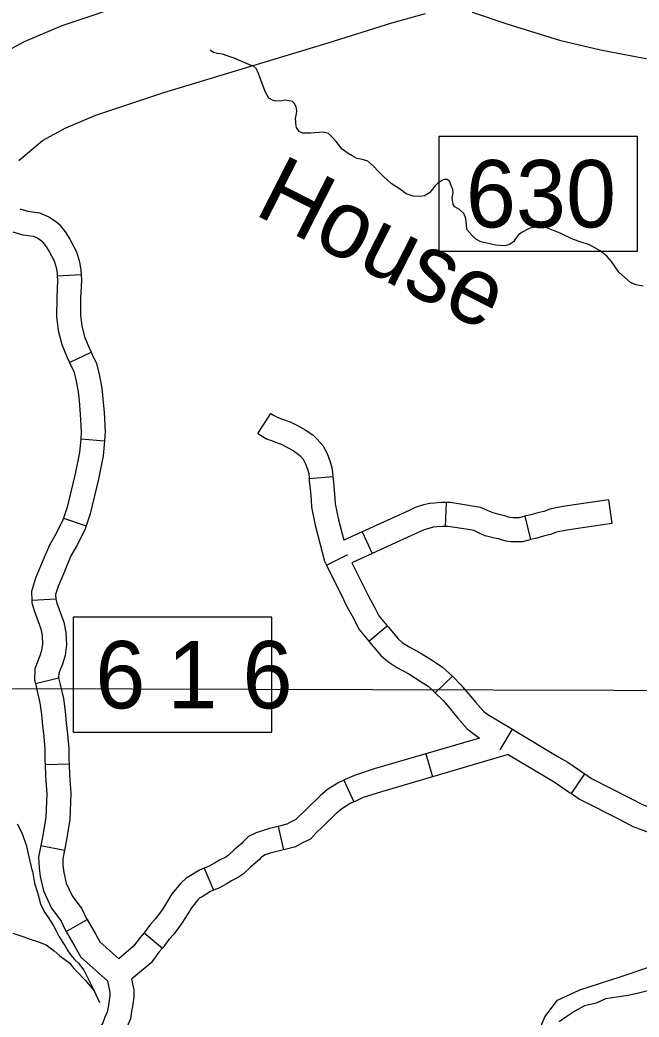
# Model space of a CAD drawing. Extents: x -492261 to -432772, y 1441225 to 1452922.
# Drawn here: x -464243.6 to -464132.7, y 1451313.1 to 1451491.7 of the extents above; entities that cross this region are included whole.
import ezdxf

# ---------------------------------------------------------------- set-up
doc = ezdxf.new("R2010")
doc.units = 0
doc.layers.add('Default', color=7, linetype='Continuous')

msp = doc.modelspace()

# ---------------------------------------------------------------- linework, layer by layer
at = {"layer": 'Default'}
for p, q in [((-464236.88, 1451445.9), (-464232.6, 1451446.1)), ((-464234.68, 1451430.36), (-464230.8, 1451432.18)), ((-464200.98, 1451417.65), (-464198.64, 1451421.24)), ((-464232.68, 1451416.69), (-464228.41, 1451416.31)), ((-464191.78, 1451409.55), (-464187.51, 1451409.91)), ((-464167.23, 1451405.28), (-464167.38, 1451400.99)), ((-464138.18, 1451405.73), (-464137.57, 1451401.49)), ((-464235.79, 1451402.47), (-464231.73, 1451401.11)), ((-464153.15, 1451402.81), (-464152.15, 1451398.65)), ((-464182.25, 1451400.03), (-464180.47, 1451396.13)), ((-464188.67, 1451394.03), (-464184.84, 1451395.94)), ((-464241.44, 1451387.81), (-464237.16, 1451388.02)), ((-464181.1, 1451380.47), (-464177.81, 1451383.22)), ((-464240.8, 1451372.85), (-464236.63, 1451373.85)), ((-464169.17, 1451371.18), (-464166.12, 1451374.2)), ((-464157.55, 1451360.99), (-464155.35, 1451364.67)), ((-464170.89, 1451360.28), (-464169.69, 1451356.16)), ((-464239.06, 1451358.34), (-464234.77, 1451358.48)), ((-464144.8, 1451353.15), (-464142.4, 1451356.7)), ((-464185.53, 1451355.55), (-464183.74, 1451351.66)), ((-464197.33, 1451347.25), (-464196.33, 1451343.08)), ((-464239.82, 1451343.83), (-464235.61, 1451343.02)), ((-464210.54, 1451339.78), (-464208.88, 1451335.84)), ((-464235.26, 1451328.44), (-464231.55, 1451330.58)), ((-464221.33, 1451328.22), (-464218.05, 1451325.47))]:
    msp.add_line(p, q, dxfattribs=at)
for points in [[(-464249.21, 1451484.39), (-464242.77, 1451487.85), (-464236.03, 1451490.72), (-464222.97, 1451495.04)], [(-464243.78, 1451466.55), (-464239.52, 1451470.13), (-464235.34, 1451472.39), (-464229.98, 1451474.67), (-464217.8, 1451478.69), (-464188.35, 1451487.59), (-464176.95, 1451491.17), (-464170.92, 1451492.87)], [(-464162.57, 1451493.1), (-464156.37, 1451490.99), (-464146.94, 1451488.06), (-464139.57, 1451486.35), (-464130.53, 1451484.62), (-464120.94, 1451483.25), (-464108.9, 1451483.08), (-464100.34, 1451482.21), (-464093.37, 1451481.26), (-464088.93, 1451481.06), (-464081.54, 1451481.13), (-464073.63, 1451482.95), (-464059.42, 1451485.52), (-464054.97, 1451485.57), (-464051.76, 1451485.07), (-464046.64, 1451483.57), (-464039.49, 1451480.26), (-464037.02, 1451479.36), (-464034.15, 1451478.64), (-464027.99, 1451478.02)], [(-464158.33, 1451451.38), (-464159.42, 1451451.6), (-464161.02, 1451451.98), (-464161.94, 1451452.43), (-464162.57, 1451453.11), (-464163.5, 1451454.18), (-464163.56, 1451454.98), (-464163.69, 1451456.13), (-464164.04, 1451457.04), (-464164.85, 1451457.77), (-464165.65, 1451458.22), (-464166, 1451458.73), (-464166.18, 1451459.76), (-464165.96, 1451460.79), (-464166.02, 1451461.36), (-464166.32, 1451462.05), (-464166.61, 1451462.84), (-464167.07, 1451463.12), (-464167.64, 1451463.12), (-464168.6, 1451462.59), (-464169.28, 1451461.95), (-464169.9, 1451461.09), (-464170.24, 1451460.74), (-464171.09, 1451460.22), (-464171.89, 1451460.09), (-464173.14, 1451460.14), (-464174.4, 1451460.58), (-464175.43, 1451461.31), (-464177.1, 1451462.44), (-464178.42, 1451463.68), (-464179.4, 1451464.59), (-464180.27, 1451465.49), (-464181.25, 1451466.4), (-464182.22, 1451466.73), (-464183.25, 1451466.89), (-464184.05, 1451467.34), (-464184.8, 1451467.79), (-464185.83, 1451468.57), (-464186.93, 1451469.94), (-464187.62, 1451470.73), (-464188.31, 1451471.35), (-464189.17, 1451471.63), (-464191.51, 1451471.43), (-464192.88, 1451471.41), (-464193.57, 1451471.75), (-464194.03, 1451472.43), (-464194.09, 1451472.66), (-464194.22, 1451474.03), (-464194.05, 1451474.89), (-464193.95, 1451475.35), (-464194.01, 1451475.86), (-464194.07, 1451476.09), (-464194.36, 1451476.72), (-464194.76, 1451477.11), (-464195.68, 1451477.27), (-464196.13, 1451477.33), (-464196.65, 1451477.21), (-464197.73, 1451477.14), (-464198.19, 1451477.3), (-464198.99, 1451477.69), (-464199.57, 1451478.77), (-464200.15, 1451480.14), (-464200.57, 1451481.45), (-464200.8, 1451481.96), (-464201.21, 1451482.93), (-464201.73, 1451483.44), (-464202.42, 1451483.66), (-464203.1, 1451483.94), (-464204.25, 1451484.44), (-464205.22, 1451484.83), (-464206.42, 1451485.28), (-464207.28, 1451485.55), (-464208.2, 1451485.71), (-464208.88, 1451485.88), (-464209.49, 1451486.27)], [(-464168.51, 1451450.3), (-464132.94, 1451450.3), (-464132.94, 1451470.85), (-464168.51, 1451470.85), (-464168.51, 1451450.3)], [(-464243.56, 1451457.88), (-464242.16, 1451457.45), (-464240.05, 1451457.17), (-464238.39, 1451456.47), (-464237.4, 1451455.8), (-464236.55, 1451455.14), (-464235.48, 1451453.73), (-464234.62, 1451452.45), (-464233.42, 1451450.16), (-464232.92, 1451448.37), (-464232.63, 1451446.88), (-464232.6, 1451446.1)], [(-464131.97, 1451444.01), (-464133.17, 1451444.29), (-464133.57, 1451444.4), (-464134.2, 1451444.67), (-464136.33, 1451446.54), (-464137.6, 1451448.47), (-464138.47, 1451449.37), (-464139.62, 1451450.33), (-464141.57, 1451451.4), (-464143.06, 1451451.9), (-464144.6, 1451452.45), (-464146.78, 1451453.51), (-464149.18, 1451454.46), (-464150.44, 1451454.67), (-464151.13, 1451454.67), (-464152.38, 1451454.37), (-464153.63, 1451453.72), (-464154.3, 1451453.2), (-464154.87, 1451452.45), (-464155.15, 1451451.99), (-464155.88, 1451451.47), (-464156.74, 1451451.23), (-464158.33, 1451451.38)], [(-464244.82, 1451453.78), (-464243.07, 1451453.24), (-464241.18, 1451452.99), (-464240.44, 1451452.68), (-464239.93, 1451452.34), (-464239.63, 1451452.1), (-464238.97, 1451451.24), (-464238.32, 1451450.26), (-464237.43, 1451448.57), (-464237.1, 1451447.39), (-464236.9, 1451446.37), (-464236.88, 1451445.9)], [(-464236.88, 1451445.9), (-464236.84, 1451445.07), (-464236.97, 1451441.93), (-464237, 1451438.61), (-464236.72, 1451436.1), (-464236.05, 1451433.59), (-464235.1, 1451431.25), (-464234.68, 1451430.36)], [(-464232.6, 1451446.1), (-464232.55, 1451445.08), (-464232.69, 1451441.82), (-464232.71, 1451438.84), (-464232.49, 1451436.9), (-464231.98, 1451434.96), (-464231.17, 1451432.97), (-464230.8, 1451432.18)], [(-464230.8, 1451432.18), (-464230.55, 1451431.65), (-464229.87, 1451430.2), (-464229.34, 1451427.96), (-464228.89, 1451425.77), (-464228.69, 1451423.87), (-464228.49, 1451421.42), (-464228.27, 1451417.92), (-464228.41, 1451416.31)], [(-464234.68, 1451430.36), (-464234.43, 1451429.84), (-464233.94, 1451428.78), (-464233.52, 1451427.03), (-464233.13, 1451425.11), (-464232.95, 1451423.47), (-464232.76, 1451421.11), (-464232.57, 1451417.98), (-464232.68, 1451416.69)], [(-464198.64, 1451421.24), (-464198.03, 1451420.84), (-464197.59, 1451420.61), (-464196.87, 1451420.33), (-464196.16, 1451420.07), (-464195.05, 1451419.69), (-464193.75, 1451418.99), (-464192.37, 1451418.25), (-464191.07, 1451417.31), (-464190.32, 1451416.65), (-464189.31, 1451415.51), (-464188.54, 1451414.07), (-464187.99, 1451412.55), (-464187.62, 1451411.25), (-464187.51, 1451409.91)], [(-464232.68, 1451416.69), (-464232.9, 1451414.25), (-464233.68, 1451410.4), (-464235.13, 1451404.44), (-464235.79, 1451402.47)], [(-464200.98, 1451417.65), (-464200.21, 1451417.15), (-464199.38, 1451416.71), (-464198.39, 1451416.32), (-464197.61, 1451416.03), (-464196.77, 1451415.74), (-464195.78, 1451415.21), (-464194.64, 1451414.6), (-464193.75, 1451413.96), (-464193.35, 1451413.61), (-464192.85, 1451413.05), (-464192.47, 1451412.32), (-464192.07, 1451411.23), (-464191.85, 1451410.47), (-464191.78, 1451409.55)], [(-464228.41, 1451416.31), (-464228.65, 1451413.63), (-464229.5, 1451409.46), (-464231.01, 1451403.25), (-464231.73, 1451401.11)], [(-464191.78, 1451409.55), (-464191.74, 1451409.13), (-464191.61, 1451407.75), (-464191.42, 1451405.73), (-464191.35, 1451404.47), (-464190.71, 1451401.24), (-464189.03, 1451394.75), (-464188.67, 1451394.03)], [(-464187.51, 1451409.91), (-464187.47, 1451409.51), (-464187.35, 1451408.15), (-464187.15, 1451406.05), (-464187.09, 1451405.02), (-464186.53, 1451402.2), (-464185.57, 1451398.51)], [(-464167.23, 1451405.28), (-464168.07, 1451405.3), (-464169.34, 1451405.16), (-464170.18, 1451405.09), (-464171.28, 1451404.85), (-464172.76, 1451404.36), (-464173.88, 1451403.85), (-464182.25, 1451400.03)], [(-464153.15, 1451402.81), (-464153.32, 1451402.77), (-464154.17, 1451402.54), (-464154.69, 1451402.53), (-464155.25, 1451402.53), (-464155.71, 1451402.6), (-464156.06, 1451402.67), (-464156.74, 1451402.89), (-464157.54, 1451403.07), (-464158.83, 1451403.4), (-464159.68, 1451403.77), (-464160.99, 1451404.37), (-464162.15, 1451404.59), (-464165.04, 1451405.02), (-464166.53, 1451405.25), (-464167.23, 1451405.28)], [(-464138.18, 1451405.73), (-464146.33, 1451404.55), (-464148.67, 1451404.08), (-464149.76, 1451403.66), (-464150.8, 1451403.44), (-464152.08, 1451403.07), (-464153.15, 1451402.81)], [(-464235.79, 1451402.47), (-464235.88, 1451402.19), (-464237.08, 1451399.73), (-464238.28, 1451397.61), (-464239.56, 1451394.62), (-464240.76, 1451391.71), (-464241.52, 1451389.36), (-464241.44, 1451387.81)], [(-464231.73, 1451401.11), (-464231.91, 1451400.57), (-464233.28, 1451397.74), (-464234.43, 1451395.71), (-464235.61, 1451392.95), (-464236.74, 1451390.23), (-464237.2, 1451388.79), (-464237.16, 1451388.02)], [(-464167.38, 1451400.99), (-464167.9, 1451401.01), (-464168.91, 1451400.9), (-464169.55, 1451400.84), (-464170.16, 1451400.71), (-464171.18, 1451400.37), (-464172.1, 1451399.95), (-464180.47, 1451396.13)], [(-464152.15, 1451398.65), (-464152.25, 1451398.62), (-464153.57, 1451398.26), (-464154.64, 1451398.25), (-464155.56, 1451398.24), (-464156.48, 1451398.38), (-464157.16, 1451398.52), (-464157.85, 1451398.75), (-464158.54, 1451398.9), (-464160.22, 1451399.33), (-464161.43, 1451399.85), (-464162.3, 1451400.26), (-464162.86, 1451400.36), (-464165.68, 1451400.78), (-464166.93, 1451400.98), (-464167.38, 1451400.99)], [(-464137.57, 1451401.49), (-464145.6, 1451400.32), (-464147.47, 1451399.94), (-464148.54, 1451399.54), (-464149.77, 1451399.27), (-464150.99, 1451398.92), (-464152.15, 1451398.65)], [(-464182.25, 1451400.03), (-464185.57, 1451398.51)], [(-464180.47, 1451396.13), (-464184.1, 1451394.47)], [(-464188.67, 1451394.03), (-464185.61, 1451387.9), (-464184.95, 1451386.55), (-464183.84, 1451384.55), (-464182.88, 1451382.61), (-464181.1, 1451380.47)], [(-464184.1, 1451394.47), (-464181.77, 1451389.8), (-464181.15, 1451388.53), (-464180.05, 1451386.55), (-464179.26, 1451384.96), (-464177.81, 1451383.22)], [(-464241.44, 1451387.81), (-464241.41, 1451387.29), (-464241.03, 1451385.95), (-464239.83, 1451382.68), (-464239.59, 1451381.46), (-464239.53, 1451379.99), (-464239.69, 1451378.8), (-464240, 1451377.8), (-464240.31, 1451377.05), (-464240.89, 1451375.48), (-464240.95, 1451373.47), (-464240.8, 1451372.85)], [(-464237.16, 1451388.02), (-464237.16, 1451388), (-464236.95, 1451387.28), (-464235.69, 1451383.83), (-464235.32, 1451381.97), (-464235.23, 1451379.78), (-464235.49, 1451377.88), (-464235.96, 1451376.35), (-464236.32, 1451375.49), (-464236.62, 1451374.65), (-464236.65, 1451373.91), (-464236.63, 1451373.85)], [(-464234.02, 1451364.17), (-464198.46, 1451364.17), (-464198.46, 1451384.72), (-464234.02, 1451384.72), (-464234.02, 1451364.17)], [(-464177.81, 1451383.22), (-464177.58, 1451382.95), (-464175.84, 1451380.87), (-464175.1, 1451380.23), (-464173.86, 1451379.41), (-464171.76, 1451378.3), (-464169.38, 1451376.78), (-464167.87, 1451375.79), (-464166.6, 1451374.68), (-464166.12, 1451374.2)], [(-464181.1, 1451380.47), (-464180.87, 1451380.2), (-464178.91, 1451377.86), (-464177.7, 1451376.81), (-464176.06, 1451375.72), (-464173.92, 1451374.59), (-464171.7, 1451373.18), (-464170.46, 1451372.37), (-464169.54, 1451371.56), (-464169.17, 1451371.18)], [(-464236.63, 1451373.85), (-464236.35, 1451372.69), (-464235.79, 1451370.19), (-464235.47, 1451367.83), (-464235.27, 1451365.82), (-464235.02, 1451363.8), (-464234.81, 1451361.22), (-464234.79, 1451359.17), (-464234.77, 1451358.48)], [(-464166.12, 1451374.2), (-464164.66, 1451372.71), (-464163.14, 1451370.98), (-464161.93, 1451369.46), (-464160.5, 1451367.85), (-464159.78, 1451367.32), (-464155.35, 1451364.67)], [(-464240.8, 1451372.85), (-464240.53, 1451371.72), (-464240.01, 1451369.43), (-464239.72, 1451367.33), (-464239.53, 1451365.35), (-464239.29, 1451363.36), (-464239.1, 1451361.03), (-464239.08, 1451359.08), (-464239.06, 1451358.34)], [(-464245.07, 1451371.95), (-464094.16, 1451371.57), (-463944.18, 1451364.55), (-463812, 1451356.85)], [(-464169.17, 1451371.18), (-464167.79, 1451369.79), (-464166.43, 1451368.24), (-464165.21, 1451366.7), (-464163.41, 1451364.68), (-464161.28, 1451363.08)], [(-464161.28, 1451363.08), (-464170.89, 1451360.28)], [(-464155.35, 1451364.67), (-464154.71, 1451364.29), (-464147.03, 1451359.69), (-464145.43, 1451358.76), (-464142.73, 1451356.92), (-464142.4, 1451356.7)], [(-464170.89, 1451360.28), (-464180.1, 1451357.59), (-464183.66, 1451356.41), (-464185.3, 1451355.66), (-464185.53, 1451355.55)], [(-464156.11, 1451360.13), (-464169.69, 1451356.16)], [(-464156.11, 1451360.13), (-464149.21, 1451356), (-464147.71, 1451355.13), (-464145.13, 1451353.37), (-464144.8, 1451353.15)], [(-464239.06, 1451358.34), (-464238.99, 1451356.26), (-464238.73, 1451353.08), (-464238.91, 1451348.94), (-464239.47, 1451345.66), (-464239.82, 1451343.83)], [(-464234.77, 1451358.48), (-464234.71, 1451356.5), (-464234.44, 1451353.16), (-464234.63, 1451348.49), (-464235.25, 1451344.89), (-464235.61, 1451343.02)], [(-464169.69, 1451356.16), (-464178.83, 1451353.49), (-464182.09, 1451352.42), (-464183.51, 1451351.76), (-464183.74, 1451351.66)], [(-464142.4, 1451356.7), (-464141.17, 1451355.87), (-464134.17, 1451352.28), (-464132.05, 1451351.17), (-464129.41, 1451350.2)], [(-464185.53, 1451355.55), (-464186.45, 1451355.13), (-464188.45, 1451353.87), (-464189.81, 1451352.74), (-464192.17, 1451350.44), (-464193.63, 1451349.06), (-464194.15, 1451348.49), (-464194.89, 1451348.13), (-464195.78, 1451347.65), (-464197.1, 1451347.3), (-464197.33, 1451347.25)], [(-464144.8, 1451353.15), (-464143.36, 1451352.17), (-464136.14, 1451348.48), (-464133.79, 1451347.24), (-464130.88, 1451346.18)], [(-464183.74, 1451351.66), (-464184.41, 1451351.35), (-464185.93, 1451350.4), (-464186.94, 1451349.56), (-464189.21, 1451347.35), (-464190.57, 1451346.06), (-464191.52, 1451345.01), (-464192.93, 1451344.32), (-464194.19, 1451343.63), (-464196.06, 1451343.14), (-464196.33, 1451343.08)], [(-464241.29, 1451339.28), (-464241.89, 1451341.85), (-464242.31, 1451343.73), (-464243.19, 1451346.07), (-464244, 1451347.66)], [(-464197.33, 1451347.25), (-464198.89, 1451346.87), (-464200, 1451346.55), (-464201.28, 1451346.13), (-464202.61, 1451345.45), (-464203.65, 1451344.47), (-464203.78, 1451344.29), (-464205.09, 1451343.2), (-464206.29, 1451342.08), (-464206.68, 1451341.79), (-464207.7, 1451341.27), (-464208.73, 1451340.67), (-464209.81, 1451340.09), (-464210.54, 1451339.78)], [(-464239.82, 1451343.83), (-464240.22, 1451341.76), (-464240.13, 1451339.87), (-464239.92, 1451338.27), (-464239.37, 1451335.71), (-464237.89, 1451332.62), (-464236.16, 1451330.31), (-464235.51, 1451328.89), (-464235.26, 1451328.44)], [(-464235.61, 1451343.02), (-464235.91, 1451341.45), (-464235.86, 1451340.25), (-464235.69, 1451339), (-464235.28, 1451337.1), (-464234.2, 1451334.85), (-464232.45, 1451332.5), (-464231.7, 1451330.85), (-464231.55, 1451330.58)], [(-464196.33, 1451343.08), (-464197.8, 1451342.73), (-464198.73, 1451342.46), (-464199.62, 1451342.16), (-464200.11, 1451341.91), (-464200.42, 1451341.62), (-464200.63, 1451341.33), (-464202.26, 1451339.98), (-464203.54, 1451338.79), (-464204.4, 1451338.15), (-464205.65, 1451337.5), (-464206.65, 1451336.93), (-464207.96, 1451336.22), (-464208.88, 1451335.84)], [(-464241.29, 1451339.28), (-464240.97, 1451337.11), (-464240.39, 1451335.43), (-464239.88, 1451333.43), (-464239.14, 1451331.91), (-464238.54, 1451331.05), (-464237.6, 1451329.58), (-464237.07, 1451328.57), (-464236.52, 1451327.49), (-464235.55, 1451325.92), (-464234.98, 1451325.01), (-464234.57, 1451324.41), (-464234.23, 1451323.9), (-464233.8, 1451323.42), (-464233.1, 1451322.79), (-464232.09, 1451321.5), (-464230.29, 1451317.83)], [(-464210.54, 1451339.78), (-464211.41, 1451339.42), (-464213.06, 1451338.39), (-464213.82, 1451338), (-464214.76, 1451337.12), (-464216.34, 1451335.17), (-464217.14, 1451333.91), (-464218.12, 1451332.35), (-464219.3, 1451330.72), (-464220.19, 1451329.75), (-464221.34, 1451328.21), (-464221.33, 1451328.22)], [(-464208.88, 1451335.84), (-464209.43, 1451335.6), (-464210.94, 1451334.66), (-464211.33, 1451334.46), (-464211.62, 1451334.18), (-464212.86, 1451332.66), (-464213.52, 1451331.62), (-464214.56, 1451329.95), (-464215.97, 1451328.01), (-464216.89, 1451327.01), (-464217.98, 1451325.55), (-464218.05, 1451325.47)], [(-464231.55, 1451330.58), (-464230, 1451327.92), (-464229.24, 1451326.57), (-464225.88, 1451323.58)], [(-464244.83, 1451328.14), (-464243.05, 1451327.53), (-464241.56, 1451327.03), (-464240.59, 1451326.7), (-464238.87, 1451326.09), (-464237.44, 1451324.96), (-464236.4, 1451324.12), (-464234.62, 1451322.76), (-464234.15, 1451322.14), (-464233.35, 1451321.29), (-464231.91, 1451319.76), (-464230.29, 1451317.83), (-464229.29, 1451315.73)], [(-464235.26, 1451328.44), (-464233.73, 1451325.79), (-464232.63, 1451323.84), (-464227.89, 1451319.62)], [(-464221.33, 1451328.22), (-464222.02, 1451327.4), (-464223.2, 1451325.82), (-464225.88, 1451323.58)], [(-464218.05, 1451325.47), (-464218.66, 1451324.74), (-464220.06, 1451322.86), (-464223.57, 1451319.92), (-464223.19, 1451318), (-464223.17, 1451316.66), (-464223.41, 1451315.04), (-464223.56, 1451314.17)], [(-464150.65, 1451310.55), (-464149.57, 1451313.18), (-464147.28, 1451316.16), (-464143.29, 1451317.99), (-464135.86, 1451320.39), (-464131.3, 1451321.93), (-464128.1, 1451322.33), (-464122.56, 1451322.84), (-464118.11, 1451322.16), (-464113.66, 1451320.84), (-464107.56, 1451318.21), (-464100.25, 1451314.89), (-464096.49, 1451313)], [(-464227.89, 1451319.62), (-464227.47, 1451317.55), (-464227.46, 1451316.95), (-464227.65, 1451315.7), (-464227.78, 1451314.87)], [(-464106.93, 1451313.11), (-464109.5, 1451315.69), (-464112.41, 1451317.23), (-464116.69, 1451318.44), (-464120.97, 1451318.84), (-464128.16, 1451318.55), (-464132.78, 1451317.41), (-464134.61, 1451317.01), (-464138.66, 1451316.38), (-464140.38, 1451315.64), (-464142.43, 1451315.13), (-464144.2, 1451314.21), (-464145.63, 1451313.24), (-464147, 1451312.27)], [(-464227.78, 1451314.87), (-464227.92, 1451314.03), (-464228.33, 1451313.09), (-464228.72, 1451312.09), (-464229.65, 1451310.63), (-464230.44, 1451308.79), (-464230.71, 1451307.08), (-464230.76, 1451305.79), (-464230.8, 1451303.67), (-464230.8, 1451303.15), (-464230.91, 1451302.23), (-464231.04, 1451301.88), (-464231.37, 1451301.28)], [(-464223.56, 1451314.17), (-464223.78, 1451312.81), (-464224.37, 1451311.46), (-464224.87, 1451310.15), (-464225.85, 1451308.62), (-464226.29, 1451307.59), (-464226.44, 1451306.65), (-464226.48, 1451305.66), (-464226.52, 1451303.66), (-464226.51, 1451302.92), (-464226.71, 1451301.21), (-464227.14, 1451300.07), (-464227.64, 1451299.18)]]:
    msp.add_lwpolyline(points, dxfattribs=at)
for points in [[(-464168.51, 1451450.3), (-464132.94, 1451450.3), (-464132.94, 1451470.85), (-464168.51, 1451470.85)], [(-464234.02, 1451364.17), (-464198.46, 1451364.17), (-464198.46, 1451384.72), (-464234.02, 1451384.72)]]:
    msp.add_lwpolyline(points, close=True, dxfattribs=at)

# ---------------------------------------------------------------- texts
msp.add_text('House', height=12.069, rotation=333, dxfattribs=at).set_placement((-464201.88, 1451457.02))
for s, height, p in [('630', 12.057, (-464163.7, 1451454.55)), ('6', 12.06, (-464230.07, 1451368.41)), ('1 6', 12.057, (-464217.15, 1451368.41))]:
    msp.add_text(s, height=height, dxfattribs=at).set_placement(p)

doc.saveas('drawing.dxf')
